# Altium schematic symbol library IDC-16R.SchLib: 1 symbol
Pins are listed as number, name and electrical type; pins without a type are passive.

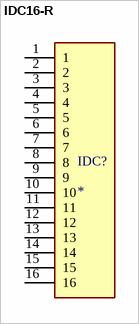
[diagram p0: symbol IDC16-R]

## IDC16-R
designator IDC?
Wire-To-Board Connector, Right Angle, AMP-LATCH Series, IDC / IDT, Header, 16, 2.54 mm; MF: TE Connectivity; Number_of_Positions: 16; MP: 2-1761605-6; Centerline_Pitch: 2.54 mm[.1 in]
footprint TE_2-1761605-6
pins: 1, 2, 3, 4, 5, 6, 7, 8, 9, 10, 11, 12, 13, 14, 15, 16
